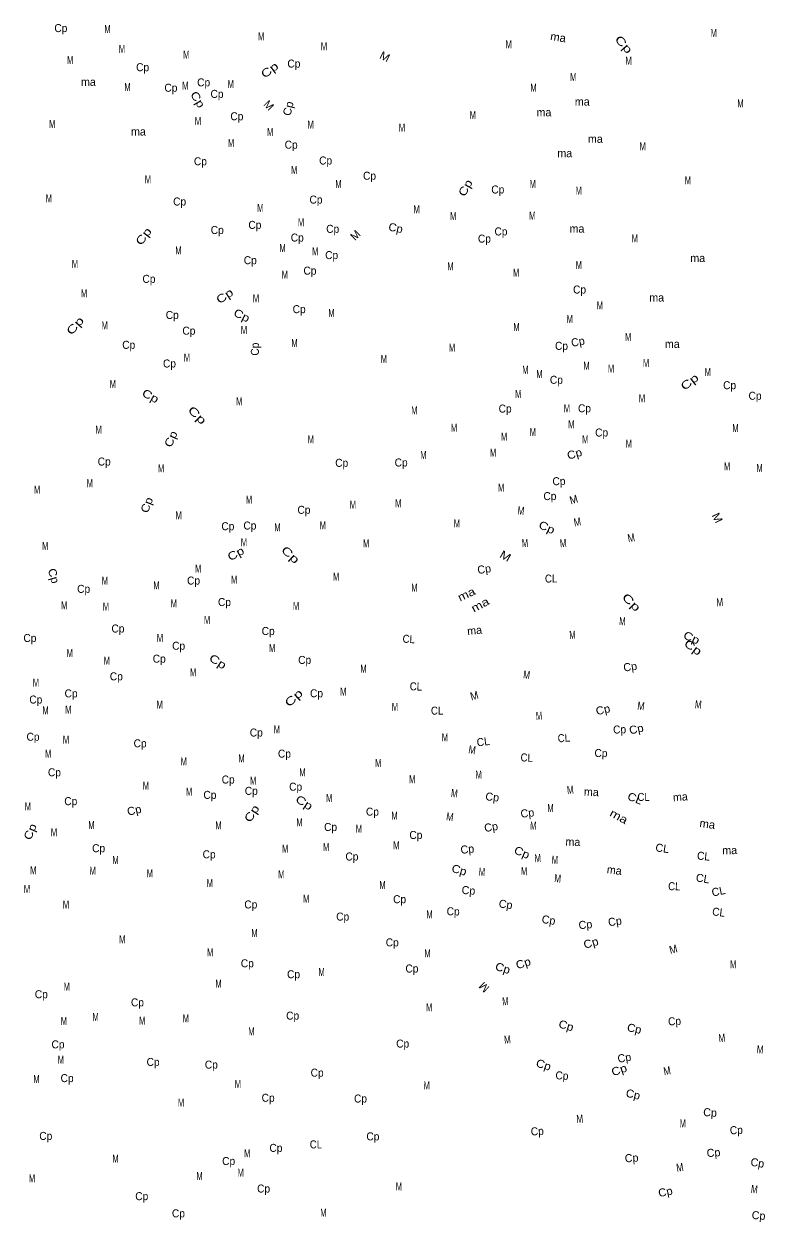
# Model space of a CAD drawing. Extents: x 713577 to 726626, y 7177731 to 7191794.
# Drawn here: x 719275 to 722794, y 7180644 to 7186332 of the extents above; entities that cross this region are included whole.
import ezdxf
from ezdxf.enums import TextEntityAlignment as Align

# ---------------------------------------------------------------- set-up
doc = ezdxf.new("R2010")
doc.units = 0
doc.header["$LTSCALE"] = 15
doc.layers.add('19', color=7, linetype='Continuous')

msp = doc.modelspace()

# ---------------------------------------------------------------- texts
at = {"layer": '19'}
for s, rotation, width, p in [('Cp', 359.99, 0.95, (719450.16, 7186293.18)), ('M', 359.99, 0.65, (719671.6, 7186288.71)), ('M', 359.99, 0.65, (720401.6, 7186253.97)), ('ma', 350.894, 1.05, (721808.93, 7186250.2)), ('Cp', 311.427, 1.45, (722108.94, 7186222.12)), ('M', 359.988, 0.65, (722550.42, 7186270.04)), ('M', 359.99, 0.65, (719740.33, 7186194.61)), ('M', 359.99, 0.65, (720699.67, 7186206.36)), ('M', 359.988, 0.65, (721576.8, 7186216.13)), ('M', 359.99, 0.65, (719494.49, 7186141.43)), ('M', 359.99, 0.65, (720045.78, 7186167.02)), ('Cp', 359.99, 0.95, (720556.82, 7186124.64)), ('M', 333.435, 1.1, (720980.38, 7186159.85)), ('M', 359.988, 0.65, (722146.5, 7186137.7)), ('Cp', 359.99, 0.95, (719838.52, 7186107.48)), ('Cp', 36.487, 1.35, (720452.73, 7186097.81)), ('M', 359.988, 0.65, (721883.6, 7186060.47)), ('M', 359.99, 0.65, (719766.59, 7186013.4)), ('Cp', 359.99, 0.95, (719972.82, 7186009.88)), ('M', 359.99, 0.65, (720041.25, 7186019.06)), ('Cp', 359.99, 0.95, (720128.37, 7186035.51)), ('M', 359.99, 0.65, (720256.98, 7186027.25)), ('M', 359.988, 0.65, (721694.65, 7186010.03)), ('Cp', 300.949, 1.25, (720084.01, 7185963.39)), ('Cp', 359.99, 0.95, (720191.71, 7185980.7)), ('Cp', 76.86, 1.05, (720548.24, 7185925.92)), ('M', 359.988, 0.65, (722677.49, 7185935.14)), ('M', 359.99, 0.65, (719409.22, 7185838.28)), ('M', 359.99, 0.65, (720101.41, 7185851.46)), ('Cp', 359.99, 0.95, (720286.07, 7185874.52)), ('M', 359.99, 0.65, (720636.53, 7185835.39)), ('M', 359.988, 0.65, (721406.36, 7185881.25)), ('M', 359.99, 0.65, (720444.34, 7185800.12)), ('M', 359.99, 0.65, (721070.05, 7185820)), ('M', 359.99, 0.65, (720258.73, 7185747.83)), ('Cp', 359.99, 0.95, (720543.7, 7185739.55)), ('M', 359.988, 0.65, (722213.12, 7185732.14)), ('Cp', 359.99, 0.95, (720707.57, 7185664.49)), ('Cp', 359.99, 0.95, (720112.94, 7185660.65)), ('M', 359.99, 0.65, (720558.49, 7185619.77)), ('M', 359.99, 0.65, (719863.77, 7185574.63)), ('M', 359.99, 0.65, (720768.43, 7185552.93)), ('Cp', 359.99, 0.95, (720915.96, 7185592.15)), ('Cp', 61.544, 1.25, (721387.8, 7185544.52)), ('M', 359.988, 0.65, (721690.96, 7185552.93)), ('M', 359.988, 0.65, (722427.74, 7185570.93)), ('Cp', 359.988, 0.95, (721525.04, 7185526.81)), ('M', 359.988, 0.65, (721909.25, 7185521.84)), ('M', 359.99, 0.65, (719393.32, 7185485.06)), ('Cp', 359.99, 0.95, (720014.18, 7185469.81)), ('M', 359.99, 0.65, (720397.21, 7185439.47)), ('Cp', 359.99, 0.95, (720661.79, 7185478.91)), ('M', 359.99, 0.65, (721139.72, 7185432.78)), ('M', 359.988, 0.65, (721313.45, 7185400.43)), ('M', 359.988, 0.65, (721688.94, 7185402)), ('Cp', 53.642, 1.35, (719858.07, 7185312.13)), ('Cp', 359.99, 0.95, (720192.84, 7185334.53)), ('Cp', 359.99, 0.95, (720371.53, 7185358.85)), ('M', 359.99, 0.65, (720590.7, 7185371.64)), ('Cp', 359.99, 0.95, (720741.08, 7185340.03)), ('Cp', 348.69, 1.05, (721036.57, 7185344.87)), ('Cp', 359.988, 0.95, (721540.19, 7185327.66)), ('Cp', 359.99, 0.95, (720572.91, 7185298.59)), ('Cp', 359.988, 0.95, (721461.58, 7185293.67)), ('M', 359.988, 0.65, (722175.71, 7185294.57)), ('M', 359.99, 0.65, (720008.48, 7185237.23)), ('M', 359.99, 0.65, (720503.14, 7185249.24)), ('M', 359.99, 0.65, (720658.13, 7185233.75)), ('Cp', 359.99, 0.95, (720736.12, 7185215.31)), ('M', 359.99, 0.65, (719517.13, 7185173.64)), ('Cp', 359.99, 0.95, (720349.79, 7185191.02)), ('M', 359.988, 0.65, (721300.44, 7185162.78)), ('M', 359.988, 0.65, (721909.83, 7185168.47)), ('Cp', 359.99, 0.95, (719868.67, 7185102.59)), ('M', 359.99, 0.65, (720513.65, 7185122.55)), ('Cp', 359.99, 0.95, (720633.11, 7185141.61)), ('M', 359.988, 0.65, (721611.94, 7185132.21)), ('Cp', 359.988, 0.95, (721913.31, 7185051.83)), ('M', 359.99, 0.65, (719560.5, 7185034.56)), ('Cp', 34.161, 1.3, (720238.8, 7185024.53)), ('M', 359.99, 0.65, (720376.74, 7185010.03)), ('Cp', 359.99, 0.95, (719979.21, 7184931.12)), ('Cp', 333.41, 1.2, (720301.03, 7184931.13)), ('Cp', 359.99, 0.95, (720581.74, 7184958.66)), ('M', 359.99, 0.65, (720735.08, 7184941.19)), ('M', 359.988, 0.65, (722009.85, 7184976.25)), ('Cp', 48.565, 1.45, (719531.99, 7184886.37)), ('M', 359.99, 0.65, (719658.36, 7184881.53)), ('M', 359.988, 0.65, (721613.87, 7184874.28)), ('M', 359.988, 0.65, (721866.76, 7184912.33)), ('Cp', 359.99, 0.95, (720058.17, 7184856.41)), ('M', 359.99, 0.65, (720319.78, 7184859.66)), ('M', 359.988, 0.65, (722144.23, 7184826.94)), ('Cp', 359.99, 0.95, (719772.52, 7184789.33)), ('Cp', 90, 0.95, (720390.42, 7184787.82)), ('M', 359.99, 0.65, (720559.67, 7184798.08)), ('M', 359.988, 0.65, (721307.95, 7184775.73)), ('Cp', 359.624, 0.95, (721827.51, 7184784.56)), ('Cp', 359.99, 0.95, (719966, 7184700.78)), ('M', 359.99, 0.65, (720048.93, 7184729.06)), ('M', 359.99, 0.65, (720984.15, 7184722.65)), ('M', 359.988, 0.65, (722229.08, 7184702.75)), ('M', 359.988, 0.65, (721656.01, 7184670.63)), ('M', 359.988, 0.65, (721722.72, 7184650.8)), ('M', 359.988, 0.65, (721946.63, 7184690.05)), ('M', 359.988, 0.65, (722062.87, 7184676.49)), ('M', 359.988, 0.65, (722522.33, 7184660.42)), ('M', 359.99, 0.65, (719696.81, 7184603.75)), ('Cp', 359.988, 0.95, (721803.29, 7184623.38)), ('Cp', 37.864, 1.4, (722447.41, 7184617.29)), ('Cp', 359.988, 0.95, (722625.88, 7184597.58)), ('Cp', 331.295, 1.25, (719866.92, 7184548.74)), ('M', 359.988, 0.65, (721622.3, 7184556.37)), ('M', 359.988, 0.65, (722209.8, 7184534.78)), ('Cp', 359.988, 0.95, (722746.74, 7184547.69)), ('Cp', 315, 1.5, (720084.42, 7184460.89)), ('M', 359.99, 0.65, (720297.35, 7184521.7)), ('M', 359.99, 0.65, (721128.9, 7184478.45)), ('Cp', 359.988, 0.95, (721559.87, 7184486.71)), ('M', 359.988, 0.65, (721853.46, 7184487.63)), ('Cp', 359.988, 0.95, (721936.68, 7184487.95)), ('M', 359.988, 0.65, (721874.25, 7184411.67)), ('M', 359.99, 0.65, (719629.64, 7184385.92)), ('Cp', 66.169, 1.2, (719989.99, 7184353.85)), ('M', 359.988, 0.65, (721317.45, 7184395.61)), ('M', 359.988, 0.65, (721555.22, 7184353.29)), ('M', 359.988, 0.65, (721691.61, 7184375.38)), ('Cp', 359.988, 0.95, (722018.23, 7184373)), ('M', 359.988, 0.65, (722653.71, 7184393.88)), ('M', 359.99, 0.65, (720637.24, 7184340)), ('M', 359.988, 0.65, (721940.61, 7184340.32)), ('M', 359.988, 0.65, (722147.34, 7184319.47)), ('M', 359.99, 0.65, (721171.64, 7184266.19)), ('M', 359.988, 0.65, (721502.69, 7184277.67)), ('Cp', 16.343, 1.1, (721894.61, 7184272.71)), ('Cp', 359.99, 0.95, (719655.94, 7184235.2)), ('M', 359.99, 0.65, (719926.43, 7184202.57)), ('Cp', 359.99, 0.95, (720783.99, 7184229.07)), ('Cp', 359.99, 0.95, (721066, 7184230.67)), ('M', 359.988, 0.65, (722613.96, 7184212.37)), ('M', 359.988, 0.65, (722768.27, 7184204.95)), ('M', 359.99, 0.65, (719587.8, 7184132.54)), ('Cp', 1.448, 0.95, (721816.01, 7184142.14)), ('M', 359.99, 0.65, (719337.37, 7184101.98)), ('M', 359.988, 0.65, (721541.29, 7184111.88)), ('Cp', 0.906, 0.95, (721772.82, 7184071.28)), ('Cp', 69.115, 1.15, (719875.97, 7184041.25)), ('M', 359.99, 0.65, (720343.99, 7184054.74)), ('M', 359.99, 0.65, (720837.26, 7184029.98)), ('M', 359.99, 0.65, (721052.81, 7184037.25)), ('M', 16.046, 0.9, (721890.7, 7184055.79)), ('M', 359.99, 0.65, (720009.64, 7183979.78)), ('Cp', 359.99, 0.95, (720604.61, 7184006)), ('M', 354.199, 0.75, (721633.13, 7184002.27)), ('M', 296.048, 1.1, (722550.19, 7183978.46)), ('Cp', 359.99, 0.95, (720243.27, 7183928.07)), ('Cp', 359.99, 0.95, (720347.92, 7183931.34)), ('M', 359.99, 0.65, (720478.89, 7183923.42)), ('M', 359.99, 0.65, (720694.1, 7183932.93)), ('M', 359.99, 0.65, (721330.86, 7183941.38)), ('Cp', 335.221, 1.2, (721750.18, 7183924.55)), ('M', 9.21, 0.8, (721905.71, 7183949.09)), ('M', 359.99, 0.65, (720319.6, 7183851.71)), ('M', 359.99, 0.65, (720899.76, 7183846.35)), ('M', 3.208, 0.7, (721655.5, 7183848.5)), ('M', 5.495, 0.75, (721837.51, 7183848.11)), ('M', 9.986, 0.8, (722161.75, 7183873.85)), ('M', 359.99, 0.65, (719375.83, 7183834.77)), ('Cp', 28.679, 1.25, (720290.11, 7183800.14)), ('Cp', 317.02, 1.45, (720527.56, 7183797.65)), ('M', 330.088, 1.2, (721551.93, 7183789.19)), ('M', 359.99, 0.65, (720102.4, 7183727.36)), ('Cp', 286.953, 1.1, (719398.13, 7183706.12)), ('Cp', 359.99, 0.95, (720080.34, 7183670.11)), ('M', 359.99, 0.65, (720273.18, 7183675.01)), ('M', 359.99, 0.65, (720757.57, 7183688.75)), ('CL', 1, 0.9, (721778.48, 7183679.74)), ('Cp', 359.99, 0.95, (719558.42, 7183630.71)), ('M', 359.99, 0.65, (719659.46, 7183669.19)), ('M', 359.99, 0.65, (719904.28, 7183648.09)), ('M', 359.99, 0.65, (721129.09, 7183637.09)), ('M', 359.99, 0.65, (719986.53, 7183561.53)), ('Cp', 359.99, 0.95, (720227.02, 7183568.14)), ('ma', 25.211, 1.2, (721384.2, 7183607.07)), ('ma', 28.277, 1.25, (721450.29, 7183557.51)), ('Cp', 315.508, 1.5, (722146.16, 7183572.51)), ('M', 4.252, 0.75, (722580.7, 7183567.36)), ('M', 359.99, 0.65, (719466.27, 7183553.07)), ('M', 359.99, 0.65, (719664.37, 7183546.78)), ('M', 359.99, 0.65, (720567.02, 7183549.26)), ('Cp', 359.99, 0.95, (719721.28, 7183442.45)), ('M', 359.99, 0.65, (720144.48, 7183482.86)), ('M', 356.865, 0.7, (722115.63, 7183476.9)), ('Cp', 359.99, 0.95, (719303.35, 7183397.44)), ('M', 359.99, 0.65, (719921.02, 7183397.67)), ('Cp', 359.99, 0.95, (720434.64, 7183430.62)), ('CL', 356.558, 0.9, (721101.22, 7183392.89)), ('M', 2.137, 0.7, (721880.12, 7183412.78)), ('Cp', 336.361, 1.2, (722437.82, 7183400.58)), ('Cp', 359.99, 0.95, (720009.47, 7183360.6)), ('M', 359.99, 0.65, (720453.78, 7183349.53)), ('Cp', 324.015, 1.35, (722441.1, 7183356.48)), ('M', 359.99, 0.65, (719492.56, 7183326)), ('M', 359.99, 0.65, (719668.27, 7183290.43)), ('Cp', 359.99, 0.95, (719917.38, 7183299.27)), ('Cp', 326.978, 1.3, (720185.5, 7183288.79)), ('Cp', 359.99, 0.95, (720608.04, 7183293.37)), ('Cp', 359.99, 0.95, (719713.67, 7183215.4)), ('M', 359.99, 0.65, (720078.29, 7183234.75)), ('M', 359.99, 0.65, (720887.41, 7183251.45)), ('M', 352.824, 0.75, (721659.86, 7183222.99)), ('M', 359.99, 0.65, (719331.95, 7183185.52)), ('CL', 358.351, 0.9, (721135.78, 7183167.48)), ('Cp', 359.99, 0.95, (719331.27, 7183105.22)), ('Cp', 359.99, 0.95, (719498.78, 7183134.48)), ('Cp', 42.948, 1.45, (720568.73, 7183118.01)), ('Cp', 359.99, 0.95, (720664.28, 7183135)), ('M', 359.99, 0.65, (720791.63, 7183143.21)), ('M', 14.873, 0.9, (721418.25, 7183124.41)), ('M', 359.99, 0.65, (719377.6, 7183054.28)), ('M', 359.99, 0.65, (719485.6, 7183057.82)), ('M', 359.99, 0.65, (719919.32, 7183081.1)), ('M', 359.99, 0.65, (721036.78, 7183070.44)), ('CL', 0.432, 0.9, (721237.03, 7183052.67)), ('Cp', 13.654, 1.05, (722028.86, 7183057.48)), ('M', 352.709, 0.8, (722202.77, 7183075.3)), ('M', 354.901, 0.75, (722475.75, 7183082.2)), ('M', 0.979, 0.7, (721721.11, 7183027.92)), ('Cp', 359.99, 0.95, (720378.29, 7182948.54)), ('M', 359.99, 0.65, (720476.09, 7182963.53)), ('Cp', 2.373, 0.95, (722104.16, 7182963.31)), ('Cp', 12.396, 1.05, (722186.89, 7182965.68)), ('Cp', 359.99, 0.95, (719318.01, 7182928.58)), ('M', 359.99, 0.65, (719474.72, 7182914.67)), ('Cp', 359.99, 0.95, (719826.43, 7182897.3)), ('M', 359.99, 0.65, (721274.01, 7182925.93)), ('CL', 7.206, 0.95, (721458.14, 7182905.17)), ('CL', 3.932, 0.9, (721840.06, 7182922.88)), ('M', 359.99, 0.65, (719390.14, 7182847.89)), ('M', 359.99, 0.65, (720308.24, 7182825.35)), ('Cp', 359.99, 0.95, (720511.87, 7182848.41)), ('M', 350.542, 0.8, (721400.22, 7182866.94)), ('CL', 357.232, 0.9, (721661.69, 7182829.73)), ('Cp', 359.139, 0.95, (722014.92, 7182851.26)), ('Cp', 359.99, 0.95, (719419.67, 7182759.75)), ('M', 359.99, 0.65, (720033.79, 7182811.25)), ('M', 359.99, 0.65, (720957.42, 7182803.9)), ('Cp', 359.99, 0.95, (720244.65, 7182725.45)), ('M', 359.99, 0.65, (720363.44, 7182720.1)), ('M', 359.99, 0.65, (720597.41, 7182760.2)), ('M', 359.99, 0.65, (721118.65, 7182727.2)), ('M', 1.704, 0.7, (721435.17, 7182748.47)), ('M', 359.99, 0.65, (719854.1, 7182696.43)), ('M', 359.99, 0.65, (720059.36, 7182667.5)), ('Cp', 359.99, 0.95, (720158.08, 7182652.67)), ('Cp', 359.99, 0.95, (720354.54, 7182671.72)), ('Cp', 359.99, 0.95, (720565.15, 7182691.43)), ('M', 354.007, 0.75, (721317.16, 7182660.44)), ('M', 4.992, 0.75, (721871.01, 7182677.09)), ('M', 359.99, 0.65, (719293.6, 7182597.87)), ('Cp', 359.99, 0.95, (719497.3, 7182622.84)), ('Cp', 327.248, 1.3, (720595.73, 7182619.06)), ('M', 359.99, 0.65, (720724.74, 7182638.42)), ('M', 359.677, 0.65, (721775.19, 7182589.88)), ('CL', 338.187, 1.1, (722170, 7182637.53)), ('CL', 0.325, 0.9, (722217.59, 7182643.01)), ('Cp', 13.214, 1.05, (719802.79, 7182580.23)), ('Cp', 57.633, 1.3, (720372.54, 7182572.92)), ('Cp', 359.99, 0.95, (720929.74, 7182572.9)), ('M', 359.99, 0.65, (721034.71, 7182554.13)), ('M', 351.647, 0.8, (721294.95, 7182548.78)), ('ma', 331.411, 1.25, (722090.99, 7182552.66)), ('Cp', 66.711, 1.2, (719321.82, 7182489.19)), ('M', 359.99, 0.65, (719595.42, 7182509.24)), ('M', 359.99, 0.65, (720198.86, 7182507.87)), ('M', 359.99, 0.65, (720583.22, 7182522.94)), ('Cp', 359.99, 0.95, (720730.97, 7182500.21)), ('M', 359.99, 0.65, (720865.56, 7182491.63)), ('M', 358.169, 0.7, (721693.01, 7182506.62)), ('ma', 352.188, 1.05, (722517.81, 7182514.57)), ('M', 359.99, 0.65, (719417.71, 7182474.71)), ('Cp', 359.99, 0.95, (721136.18, 7182462.3)), ('Cp', 359.99, 0.95, (719629.55, 7182399.38)), ('Cp', 359.99, 0.95, (720154.22, 7182370.33)), ('M', 359.99, 0.65, (720515.54, 7182396.92)), ('M', 359.99, 0.65, (720710.02, 7182404.46)), ('M', 359.99, 0.65, (721043.37, 7182412.95)), ('Cp', 336.87, 1.15, (721632.55, 7182380.98)), ('CL', 354.089, 0.95, (722500.26, 7182362.09)), ('M', 359.99, 0.65, (719710.16, 7182343.43)), ('Cp', 359.99, 0.95, (720832.43, 7182360.01)), ('M', 3.37, 0.7, (721716.2, 7182352.15)), ('M', 358.941, 0.7, (721796.14, 7182344.08)), ('M', 359.99, 0.65, (719319.35, 7182294.46)), ('M', 359.99, 0.65, (719601.56, 7182292.44)), ('M', 359.99, 0.65, (719872.71, 7182280.54)), ('M', 359.99, 0.65, (720496.89, 7182275.17)), ('Cp', 343.964, 1.1, (721336.71, 7182297.03)), ('M', 358.211, 0.7, (721449.37, 7182287.37)), ('M', 358.703, 0.7, (721649.59, 7182290.52)), ('M', 354.888, 0.75, (721808.17, 7182256.37)), ('M', 359.99, 0.65, (719289.26, 7182205.29)), ('M', 359.99, 0.65, (720157.68, 7182233.44)), ('M', 359.99, 0.65, (720977.53, 7182225.07)), ('CL', 358.309, 0.9, (722362.72, 7182218.69)), ('M', 359.99, 0.65, (720615.34, 7182159.12)), ('Cp', 359.99, 0.95, (721058.79, 7182157.26)), ('M', 359.99, 0.65, (719474.51, 7182131.87)), ('Cp', 359.99, 0.95, (720352.28, 7182132.38)), ('M', 359.99, 0.65, (721200.94, 7182085.5)), ('Cp', 358.357, 0.95, (721312.56, 7182099.49)), ('CL', 352.856, 0.95, (722572.06, 7182096.17)), ('Cp', 359.99, 0.95, (720788.61, 7182074.71)), ('M', 359.99, 0.65, (719742.02, 7181966.63)), ('M', 359.99, 0.65, (720369.56, 7181996.47)), ('Cp', 359.99, 0.95, (721023.88, 7181952.26)), ('Cp', 16.344, 1.1, (721972.64, 7181950.5)), ('M', 14.222, 0.9, (722362.96, 7181920.82)), ('M', 359.99, 0.65, (720159.27, 7181904.69)), ('Cp', 359.99, 0.95, (720335.77, 7181853)), ('M', 359.99, 0.65, (721191.36, 7181900.89)), ('Cp', 18.245, 1.1, (721651.9, 7181854.37)), ('Cp', 359.99, 0.95, (720555.25, 7181800.97)), ('M', 359.99, 0.65, (720688.4, 7181811.47)), ('Cp', 359.99, 0.95, (721117.31, 7181828.18)), ('Cp', 342.474, 1.1, (721543.4, 7181830.92)), ('M', 359.99, 0.65, (719478.06, 7181742.25)), ('M', 359.99, 0.65, (720199.06, 7181756.28)), ('Cp', 359.99, 0.95, (719357.42, 7181706.08)), ('Cp', 359.99, 0.95, (719813.83, 7181667.5)), ('M', 359.99, 0.65, (721199.22, 7181644.55)), ('M', 3.099, 0.7, (721561.95, 7181673.09)), ('M', 359.99, 0.65, (719464.54, 7181579.37)), ('M', 359.99, 0.65, (719615.26, 7181598.1)), ('M', 359.99, 0.65, (719836.72, 7181581.28)), ('M', 359.99, 0.65, (720043.71, 7181591.11)), ('Cp', 359.99, 0.95, (720550.94, 7181604.51)), ('Cp', 3.047, 0.95, (722365.24, 7181578.39)), ('M', 359.99, 0.65, (720355, 7181529.19)), ('Cp', 343.383, 1.1, (721844.47, 7181558.41)), ('Cp', 347.71, 1.05, (722169.59, 7181543.66)), ('Cp', 359.99, 0.95, (719436.68, 7181468.15)), ('Cp', 359.99, 0.95, (721073.48, 7181471.81)), ('M', 4.458, 0.75, (721572.13, 7181491.84)), ('M', 5.269, 0.75, (722591.17, 7181498.69)), ('M', 359.99, 0.65, (719450.36, 7181395.42)), ('M', 354.623, 0.75, (722768.81, 7181444.27)), ('Cp', 359.99, 0.95, (719888.15, 7181384.48)), ('Cp', 359.99, 0.95, (720164.9, 7181371.93)), ('Cp', 342.189, 1.1, (721736.79, 7181372.04)), ('Cp', 19.463, 1.15, (722107.43, 7181347.77)), ('M', 10.012, 0.8, (722332.25, 7181342.82)), ('M', 359.99, 0.65, (719334.51, 7181303.96)), ('Cp', 359.99, 0.95, (719479.76, 7181307.88)), ('Cp', 359.99, 0.95, (720667.06, 7181333.67)), ('Cp', 356.922, 0.95, (721828.81, 7181320.09)), ('M', 359.99, 0.65, (720291.12, 7181279.77)), ('M', 359.99, 0.65, (721187.63, 7181273.36)), ('Cp', 346.41, 1.05, (722163.22, 7181231.58)), ('M', 359.99, 0.65, (720020.93, 7181191.62)), ('Cp', 359.99, 0.95, (720434.38, 7181214.59)), ('Cp', 359.99, 0.95, (720873.03, 7181210.89)), ('M', 5.074, 0.75, (721916.22, 7181114.86)), ('Cp', 2.911, 0.95, (721713.54, 7181055.87)), ('M', 359.529, 0.65, (722403.07, 7181093)), ('Cp', 2.352, 0.95, (722658.59, 7181061.16)), ('Cp', 359.99, 0.95, (719378.69, 7181033.45)), ('Cp', 359.99, 0.95, (720931.9, 7181031.21)), ('M', 359.99, 0.65, (720335.15, 7180951.35)), ('Cp', 359.99, 0.95, (720471.52, 7180976.66)), ('CL', 359.99, 0.9, (720661.4, 7180993.08)), ('M', 359.99, 0.65, (719709.91, 7180925.79)), ('Cp', 359.99, 0.95, (720247.09, 7180914.18)), ('M', 8.664, 0.8, (722392.5, 7180884.3)), ('M', 359.99, 0.65, (719313.5, 7180832.2)), ('M', 359.99, 0.65, (720108.73, 7180843.12)), ('M', 359.99, 0.65, (720304.2, 7180859.21)), ('Cp', 359.99, 0.95, (720412.92, 7180783.51)), ('M', 359.99, 0.65, (721055.46, 7180793.27)), ('M', 352.991, 0.75, (722741.1, 7180780.73)), ('Cp', 359.99, 0.95, (719834.4, 7180747.41)), ('Cp', 11.48, 1.05, (722324.62, 7180768.43)), ('Cp', 359.99, 0.95, (720008.47, 7180665.77)), ('M', 359.99, 0.65, (720696.75, 7180668.94))]:
    msp.add_text(s, height=38, rotation=rotation, dxfattribs=dict(at, width=width)).set_placement(p, align=Align.CENTER)
for s, rotation, p in [('ma', 359.99, (719580.95, 7186037.83)), ('M', 315, (720423.99, 7185931.9)), ('ma', 359.988, (721926.11, 7185944.28)), ('ma', 359.988, (721744.14, 7185893.47)), ('ma', 359.99, (719818.5, 7185802.09)), ('ma', 359.988, (721988.16, 7185767.59)), ('ma', 359.988, (721843.17, 7185699.26)), ('ma', 359.988, (721900.88, 7185341.26)), ('M', 45, (720862.25, 7185315.45)), ('ma', 359.988, (722474.49, 7185201.44)), ('ma', 359.988, (722279.61, 7185013.9)), ('Cp', 11.098, (721908.86, 7184804.51)), ('ma', 359.988, (722353.54, 7184793.61)), ('Cp', 8.889, (721463.12, 7183724.83)), ('ma', 5.762, (721416.72, 7183433.55)), ('Cp', 8.189, (722156.27, 7183261.29)), ('ma', 357.366, (721968.49, 7182666.78)), ('Cp', 353.709, (721496.92, 7182642.87)), ('ma', 4.229, (722393.28, 7182643.38)), ('Cp', 6.768, (721667.64, 7182566.47)), ('Cp', 10.407, (721496.45, 7182500.57)), ('ma', 357.793, (721881.07, 7182429.7)), ('Cp', 6.698, (721382.52, 7182394.86)), ('CL', 351.937, (722303.87, 7182399.49)), ('ma', 1.105, (722626.7, 7182389.83)), ('ma', 352.747, (722076.15, 7182295.4)), ('CL', 350.347, (722495.48, 7182256.2)), ('Cp', 355.667, (721384.62, 7182199.41)), ('CL', 11.607, (722576.61, 7182195.27)), ('Cp', 351.847, (721559.9, 7182133.22)), ('Cp', 351.329, (721763.67, 7182058.92)), ('Cp', 5.412, (721942.82, 7182036.62)), ('Cp', 8.31, (722083.87, 7182052.28)), ('M', 136.107, (721472.86, 7181772.04)), ('Cp', 9.45, (722128.96, 7181404.65)), ('Cp', 355.997, (722531.87, 7181144.91)), ('Cp', 4.886, (722550.96, 7180954.24)), ('Cp', 3.596, (722161.7, 7180928.76)), ('Cp', 350.298, (722755.05, 7180906.05)), ('Cp', 355.437, (722762.12, 7180655.92))]:
    msp.add_text(s, height=38, rotation=rotation, dxfattribs=at).set_placement(p, align=Align.CENTER)
at = {"layer": '19', "width": 0.65}
msp.add_text('M', height=38, dxfattribs=at).set_placement((722642.9, 7181848.21), align=Align.CENTER)

doc.saveas('drawing.dxf')
